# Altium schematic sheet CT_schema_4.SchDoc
size 276 x 169 mm
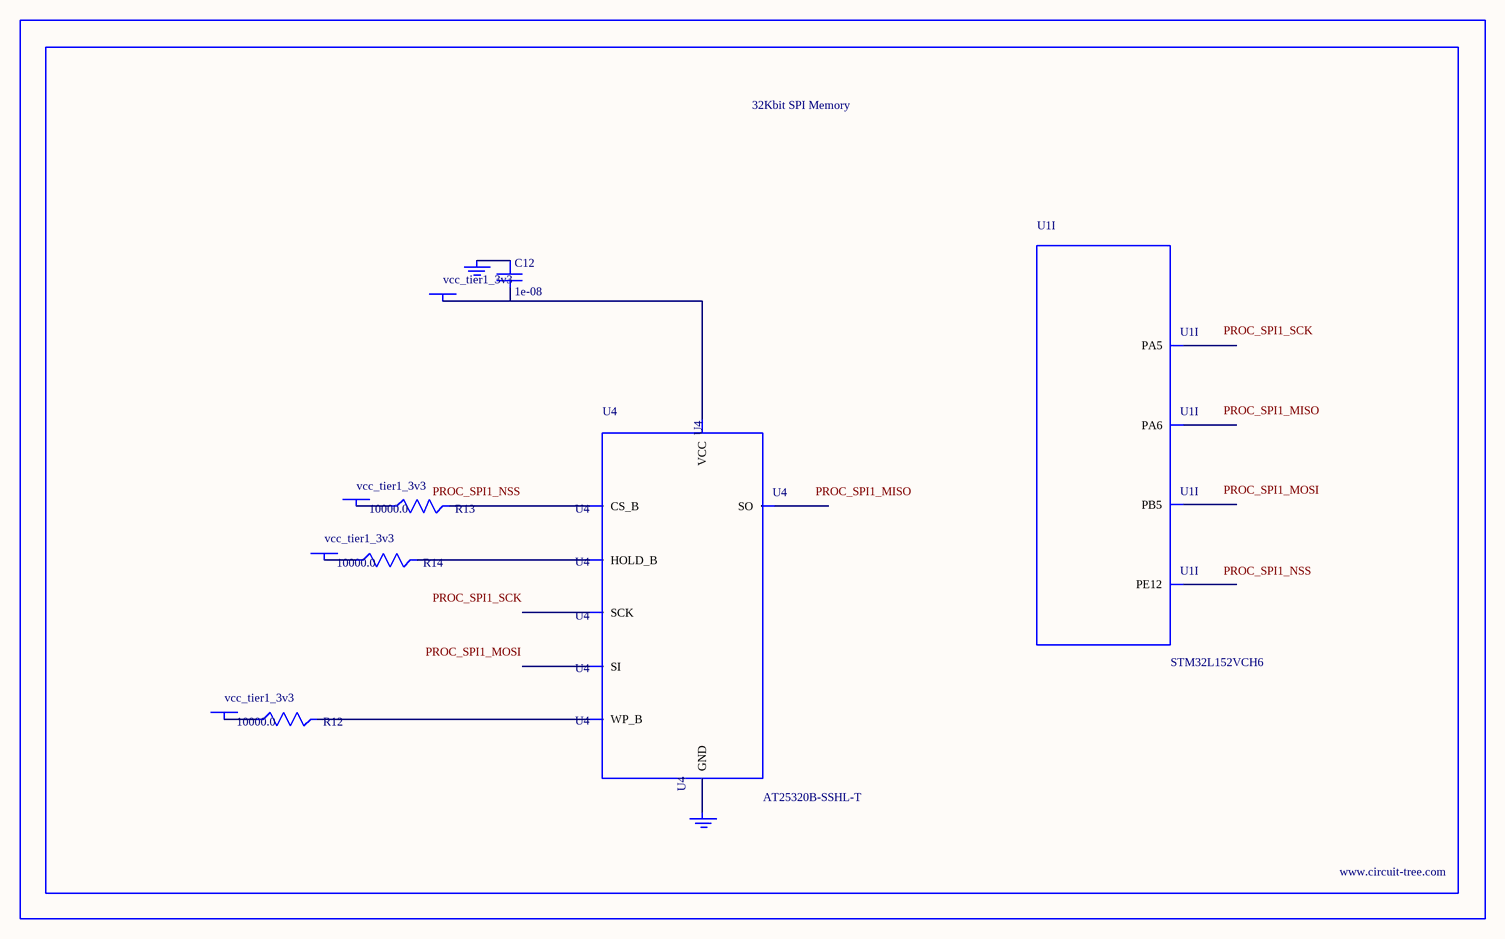
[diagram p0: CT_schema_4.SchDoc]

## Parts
BORDER3  (no value)
C12  1e-08  [C0402]
GND_INSTANCE_3_0  (no value)
GND_INSTANCE_3_1  (no value)
POWER_INSTANCE_3_0  vcc_tier1_3v3
POWER_INSTANCE_3_1  vcc_tier1_3v3
POWER_INSTANCE_3_2  vcc_tier1_3v3
POWER_INSTANCE_3_3  vcc_tier1_3v3
R12  10000.0  [R0603]
R13  10000.0  [R0603]
R14  10000.0  [R0603]
U1  STM32L152VCH6  [UFBGA100]  (part I of 11)
U4  AT25320B-SSHL-T  [SOIC-8]

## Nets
NetC12_1: C12.1 GND_INSTANCE_3_0.0(GND)
NetC12_2: C12.2 POWER_INSTANCE_3_3.0(PWR) U4.8(VCC)
NetGND_INSTANCE_3_1_0: GND_INSTANCE_3_1.0(GND) U4.4(GND)
NetPOWER_INSTANCE_3_0_0: POWER_INSTANCE_3_0.0(PWR) R13.1
NetPOWER_INSTANCE_3_1_0: POWER_INSTANCE_3_1.0(PWR) R12.1
NetPOWER_INSTANCE_3_2_0: POWER_INSTANCE_3_2.0(PWR) R14.1
NetR12_2: R12.2 U4.3(WP_B)
NetR13_2: R13.2 U4.1(CS_B)
NetR14_2: R14.2 U4.7(HOLD_B)

Not connected (* = marked no-connect by the designer): U1 C5(PB5) K4(PA5) L4(PA6) L9(PE12); U4 2(SO) 5(SI) 6(SCK)

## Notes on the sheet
- Labels drawn without touching a wire or pin: PROC_SPI1_MISO, PROC_SPI1_MOSI, PROC_SPI1_NSS, PROC_SPI1_SCK

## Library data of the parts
BORDER3 = BORDER_PAGE3
C12 = C0402C103K3RAC
GND_INSTANCE_3_0 GND_INSTANCE_3_1 = GND
POWER_INSTANCE_3_0-POWER_INSTANCE_3_3 = PWR
R12-R14 = RC0603JR-0710KL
